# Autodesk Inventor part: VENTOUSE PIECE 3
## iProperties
Created: 2004-11
Part Number: VENTOUSE PIECE 3
Document SubType Name: Modeling
Designer: Bruno
Manufacturer: Standard
Standards Organization: Custom
Author: Bruno
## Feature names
1. Base1
